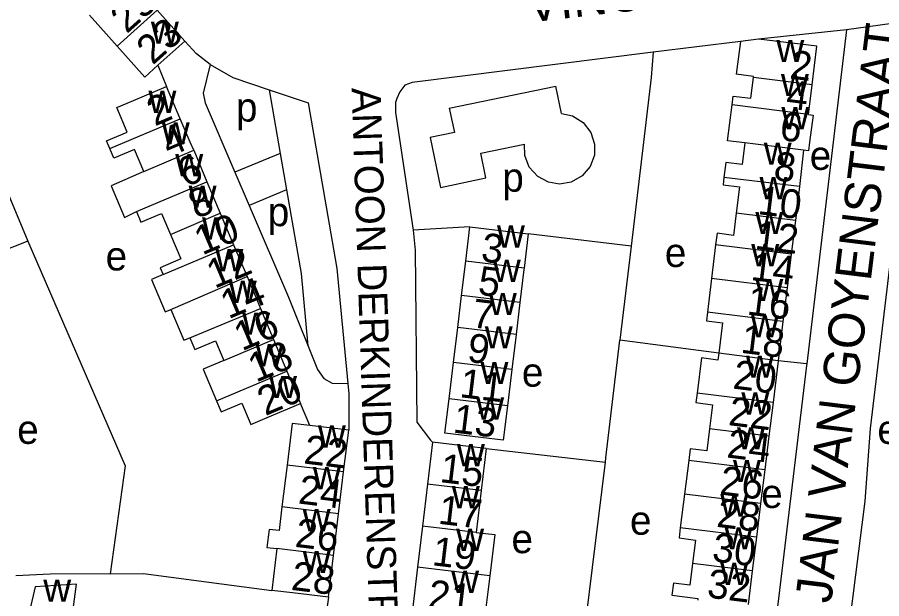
# Model space of a CAD drawing. Extents: x 161775 to 163181, y 382878 to 383925.
# Drawn here: x 162735.4 to 162855, y 383186.8 to 383267.3 of the extents above; entities that cross this region are included whole.
import ezdxf

# ---------------------------------------------------------------- set-up
doc = ezdxf.new("R2010")
doc.units = 0
for name, color, linetype in [('BLT_Basislijn', 7, 'Continuous'), ('BLT_Bebouwing', 7, 'Continuous'), ('BLT_Centroide', 7, 'Continuous'), ('BLT_Huisnummer', 7, 'Continuous'), ('BLT_Huisnummer_ tussenligend', 7, 'Continuous'), ('BLT_Onderverdeling_panden', 7, 'Continuous'), ('BLT_Straatnaam', 7, 'Continuous'), ('BLT_Vlakafsluiter', 7, 'Continuous')]:
    doc.layers.add(name, color=color, linetype=linetype)

msp = doc.modelspace()

# ---------------------------------------------------------------- linework, layer by layer
at = {"layer": 'BLT_Basislijn'}
for p, q in [((162850.08, 383265.57), (162837.91, 383264.26)), ((162835.43, 383263.94), (162823.34, 383262.45)), ((162754.83, 383260.65), (162756.03, 383257.73)), ((162795.14, 383254.7), (162809.86, 383257.75)), ((162810.65, 383253.97), (162809.86, 383257.75)), ((162795.14, 383254.7), (162795.84, 383251.34)), ((162795.84, 383251.34), (162792.48, 383250.64)), ((162792.48, 383250.64), (162793.91, 383243.74)), ((162799.49, 383248.49), (162805.55, 383249.74)), ((162771.75, 383248.43), (162765.48, 383245.83)), ((162771.75, 383248.43), (162772.63, 383243.38)), ((162800.21, 383245.04), (162799.49, 383248.49)), ((162765.48, 383245.83), (162767.45, 383241.23)), ((162793.91, 383243.74), (162800.21, 383245.04)), ((162772.63, 383243.38), (162767.45, 383241.23)), ((162797.99, 383238.29), (162790.12, 383237.8)), ((162820.29, 383235.6), (162806.06, 383237.31)), ((162736.81, 383236.3), (162732.43, 383234.55)), ((162820.29, 383235.6), (162818.74, 383222.6)), ((162832.43, 383220.77), (162818.74, 383222.6)), ((162844.59, 383219.29), (162840.64, 383219.75)), ((162775.84, 383210.77), (162774.56, 383213.82)), ((162800.24, 383207.59), (162816.74, 383205.68)), ((162813.91, 383182.7), (162816.74, 383205.68)), ((162778.41, 383186.99), (162778.14, 383185.09))]:
    msp.add_line(p, q, dxfattribs=at)
for points in [[(162850.08, 383265.57), (162844.59, 383219.29)], [(162762.03, 383260.74), (162760.17, 383262.24), (162758.54, 383263.98)], [(162823.34, 383262.45), (162789.99, 383258.28), (162789, 383257.91), (162788.28, 383256.97), (162787.9, 383256.06), (162787.71, 383255.49), (162787.71, 383254.12), (162790.12, 383237.8)], [(162823.34, 383262.45), (162823.08, 383258.97), (162820.29, 383235.6)], [(162762.03, 383260.74), (162761.1, 383256.8), (162761.38, 383255.43), (162765.48, 383245.83)], [(162762.03, 383260.74), (162765.2, 383258.95), (162770.21, 383257.25)], [(162724.18, 383256.84), (162732, 383247.83), (162736.81, 383236.3)], [(162770.21, 383257.25), (162775.6, 383255.43), (162779.6, 383232.5), (162781.09, 383216.58)], [(162770.21, 383257.25), (162771.75, 383248.43)], [(162810.65, 383253.97), (162812.2, 383253.63), (162813.66, 383252.73), (162814.74, 383251.35), (162815.25, 383249.74), (162815.21, 383248.19), (162814.65, 383246.65), (162813.52, 383245.32), (162812.01, 383244.46), (162810.39, 383244.19), (162808.86, 383244.44), (162807.38, 383245.24), (162806.21, 383246.55), (162805.6, 383248.16), (162805.55, 383249.74)], [(162857.59, 383245.49), (162853.35, 383210.37), (162852.65, 383200.3), (162849.19, 383172.97), (162849.18, 383172.77)], [(162772.63, 383243.38), (162774.64, 383231.83), (162775.57, 383221.82)], [(162767.45, 383241.23), (162772.87, 383228.55), (162776.89, 383218.54), (162777.8, 383217.28), (162778.95, 383216.64), (162781.09, 383216.58)], [(162790.12, 383237.8), (162790.42, 383235.04), (162790.63, 383211.25), (162792.55, 383208.75), (162792.83, 383208.48)], [(162736.81, 383236.3), (162750.28, 383205.17), (162748.23, 383190.26)], [(162816.74, 383205.68), (162816.81, 383206.28), (162818.74, 383222.6)], [(162844.59, 383219.29), (162844.56, 383219.06), (162840.12, 383182.2), (162838.49, 383174.01)], [(162781.09, 383216.58), (162781.24, 383215.18), (162781.23, 383210.12)], [(162748.23, 383190.26), (162739.9, 383190.21), (162735.14, 383189.96)], [(162748.23, 383190.26), (162752.83, 383190.3), (162770.58, 383187.95)]]:
    msp.add_lwpolyline(points, dxfattribs=at)
at = {"layer": 'BLT_Bebouwing'}
for p, q in [((162749.17, 383263.3), (162745.34, 383267.58)), ((162754.71, 383268.26), (162758.54, 383263.98)), ((162758.54, 383263.98), (162754.83, 383260.65)), ((162845.34, 383257.94), (162845.99, 383263.27)), ((162757.92, 383253.24), (162756.03, 383257.73)), ((162844.83, 383253.83), (162845.34, 383257.94)), ((162759.77, 383248.87), (162761.61, 383244.51)), ((162844.16, 383248.89), (162843.6, 383243.87)), ((162761.61, 383244.51), (162763.44, 383240.16)), ((162843.6, 383243.87), (162843.02, 383239.17)), ((162763.44, 383240.16), (162765.3, 383235.77)), ((162843.02, 383239.17), (162842.45, 383234.5)), ((162797.41, 383233.52), (162797.99, 383238.29)), ((162797.99, 383238.29), (162806.06, 383237.31)), ((162806.06, 383237.31), (162805.48, 383232.55)), ((162765.3, 383235.77), (162767.15, 383231.38)), ((162831.98, 383235.8), (162831.4, 383231.13)), ((162842.45, 383234.5), (162841.87, 383229.84)), ((162796.84, 383228.76), (162797.41, 383233.52)), ((162767.15, 383231.38), (162769, 383226.99)), ((162831.4, 383231.13), (162830.88, 383226.46)), ((162841.87, 383229.84), (162841.3, 383225.18)), ((162796.31, 383224.36), (162796.84, 383228.76)), ((162804.9, 383227.79), (162804.37, 383223.39)), ((162769, 383226.99), (162770.82, 383222.67)), ((162795.72, 383219.49), (162796.31, 383224.36)), ((162841.3, 383225.18), (162840.64, 383219.75)), ((162804.37, 383223.39), (162803.78, 383218.52)), ((162770.82, 383222.67), (162772.67, 383218.3)), ((162795.11, 383214.47), (162795.72, 383219.49)), ((162840.64, 383219.75), (162839.93, 383213.97)), ((162772.67, 383218.3), (162774.56, 383213.82)), ((162803.78, 383218.52), (162803.18, 383213.5)), ((162839.93, 383213.97), (162839.35, 383209.3)), ((162781.23, 383210.12), (162775.84, 383210.77)), ((162780.52, 383204.34), (162781.23, 383210.12)), ((162839.35, 383209.3), (162838.78, 383204.64)), ((162792.83, 383208.48), (162792.13, 383202.67)), ((162800.24, 383207.59), (162799.55, 383201.78)), ((162772.69, 383205.29), (162771.99, 383199.51)), ((162828.26, 383205.93), (162827.68, 383201.27)), ((162779.82, 383198.55), (162780.52, 383204.34)), ((162838.78, 383204.64), (162838.21, 383199.97)), ((162792.13, 383202.67), (162791.43, 383196.86)), ((162799.55, 383201.78), (162798.85, 383195.97)), ((162827.68, 383201.27), (162827.1, 383196.6)), ((162838.21, 383199.97), (162837.64, 383195.31)), ((162779.12, 383192.77), (162779.82, 383198.55)), ((162791.43, 383196.86), (162790.75, 383191.15)), ((162837.64, 383195.31), (162837.06, 383190.64)), ((162771.28, 383193.73), (162770.58, 383187.95)), ((162778.41, 383186.99), (162779.12, 383192.77)), ((162790.75, 383191.15), (162790.04, 383185.25)), ((162837.06, 383190.64), (162836.49, 383185.98)), ((162800.74, 383189.96), (162800.03, 383184.05))]:
    msp.add_line(p, q, dxfattribs=at)
for points in [[(162835.43, 383263.94), (162834.84, 383259.4)], [(162837.91, 383264.26), (162835.43, 383263.94)], [(162845.99, 383263.27), (162837.91, 383264.26)], [(162754.83, 383260.65), (162753, 383259.02), (162749.17, 383263.3)], [(162834.27, 383255.15), (162834.42, 383256.38), (162836.86, 383256.07), (162837.25, 383258.95)], [(162837.25, 383258.95), (162837.24, 383259.1), (162834.84, 383259.4)], [(162748.17, 383249.12), (162747.72, 383250.17), (162750.58, 383251.38), (162749.13, 383254.8), (162751.43, 383255.78), (162756.03, 383257.73)], [(162836.05, 383249.9), (162833.65, 383250.2), (162834.27, 383255.15)], [(162759.77, 383248.87), (162759.29, 383250), (162757.92, 383253.24)], [(162844.83, 383253.83), (162845.47, 383253.74), (162845, 383250), (162844.85, 383248.8), (162844.16, 383248.89)], [(162836.05, 383249.9), (162835.68, 383246.92), (162833.4, 383247.2), (162833.14, 383245.12)], [(162752.87, 383245.96), (162751.59, 383249), (162748.73, 383247.79), (162748.17, 383249.12)], [(162752.87, 383245.96), (162748.37, 383243.94), (162750.21, 383239.58), (162751.86, 383240.39)], [(162833.14, 383245.12), (162833.01, 383244.08), (162835.29, 383243.8), (162834.84, 383240.18)], [(162751.86, 383240.39), (162752.48, 383238.92), (162755.34, 383240.13), (162756.56, 383237.23)], [(162834.84, 383240.18), (162834.45, 383237.09), (162832.18, 383237.38), (162831.98, 383235.8)], [(162756.56, 383237.23), (162758, 383233.83), (162755.14, 383232.62), (162755.55, 383231.66)], [(162805.48, 383232.55), (162805.46, 383232.35), (162804.9, 383227.79)], [(162755.55, 383231.66), (162753.94, 383230.98), (162755.83, 383226.5), (162756.62, 383226.83)], [(162756.62, 383226.83), (162758.42, 383222.58), (162759.24, 383222.93)], [(162830.88, 383226.46), (162830.73, 383225.27), (162832.95, 383225), (162832.43, 383220.77)], [(162759.24, 383222.93), (162759.93, 383221.28), (162762.8, 383222.49), (162763.95, 383219.77)], [(162832.43, 383220.77), (162832.31, 383219.83), (162830.03, 383220.12), (162829.42, 383215.26)], [(162763.95, 383219.77), (162761.09, 383218.56), (162762.93, 383214.2)], [(162829.42, 383215.26), (162829.26, 383213.94), (162831.54, 383213.65), (162831.12, 383210.32)], [(162762.93, 383214.2), (162763.59, 383212.65), (162766.45, 383213.86), (162767.69, 383210.92), (162769.95, 383211.87), (162774.56, 383213.82)], [(162803.18, 383213.5), (162802.6, 383208.73), (162799.5, 383209.11), (162794.53, 383209.71), (162795.11, 383214.47)], [(162775.84, 383210.77), (162773.4, 383211.07), (162772.69, 383205.29)], [(162831.12, 383210.32), (162830.75, 383207.27), (162828.46, 383207.56), (162828.26, 383205.93)], [(162800.24, 383207.59), (162797.8, 383207.88), (162792.83, 383208.48)], [(162771.99, 383199.51), (162771.59, 383196.22), (162770.2, 383196.39), (162769.89, 383193.9), (162771.28, 383193.73)], [(162827.1, 383196.6), (162826.93, 383195.2), (162829.21, 383194.91), (162828.81, 383191.66)], [(162798.85, 383195.97), (162801.43, 383195.7), (162800.74, 383189.96)], [(162828.81, 383191.66), (162828.43, 383188.67), (162826.15, 383188.95), (162825.94, 383187.28), (162829.55, 383186.83), (162829.52, 383186.6)], [(162737.82, 383188.43), (162737.11, 383185.26), (162742.91, 383183.96), (162743.56, 383188.81), (162737.82, 383188.43)], [(162778.41, 383186.99), (162773.45, 383187.6), (162770.58, 383187.95)]]:
    msp.add_lwpolyline(points, dxfattribs=at)
at = {"layer": 'BLT_Onderverdeling_panden'}
for p, q in [((162749.17, 383263.3), (162754.71, 383268.26)), ((162845.34, 383257.94), (162837.25, 383258.95)), ((162844.83, 383253.83), (162834.27, 383255.15)), ((162748.17, 383249.12), (162757.92, 383253.24)), ((162752.87, 383245.96), (162759.77, 383248.87)), ((162751.86, 383240.39), (162761.61, 383244.51)), ((162843.6, 383243.87), (162833.14, 383245.12)), ((162756.56, 383237.23), (162763.44, 383240.16)), ((162843.02, 383239.17), (162834.84, 383240.18)), ((162755.55, 383231.66), (162765.3, 383235.77)), ((162842.45, 383234.5), (162831.98, 383235.8)), ((162805.48, 383232.55), (162797.41, 383233.52)), ((162756.62, 383226.83), (162767.15, 383231.38)), ((162841.87, 383229.84), (162831.4, 383231.13)), ((162804.9, 383227.79), (162796.84, 383228.76)), ((162759.24, 383222.93), (162769, 383226.99)), ((162841.3, 383225.18), (162830.88, 383226.46)), ((162804.37, 383223.39), (162796.31, 383224.36)), ((162763.95, 383219.77), (162770.82, 383222.67)), ((162840.64, 383219.75), (162832.43, 383220.77)), ((162803.78, 383218.52), (162795.72, 383219.49)), ((162762.93, 383214.2), (162772.67, 383218.3)), ((162839.93, 383213.97), (162829.42, 383215.26)), ((162803.18, 383213.5), (162795.11, 383214.47)), ((162839.35, 383209.3), (162831.12, 383210.32)), ((162780.52, 383204.34), (162772.69, 383205.29)), ((162838.78, 383204.64), (162828.26, 383205.93)), ((162799.55, 383201.78), (162792.13, 383202.67)), ((162838.21, 383199.97), (162827.68, 383201.27)), ((162779.82, 383198.55), (162771.99, 383199.51)), ((162798.85, 383195.97), (162791.43, 383196.86)), ((162837.64, 383195.31), (162827.1, 383196.6)), ((162779.12, 383192.77), (162771.28, 383193.73)), ((162800.74, 383189.96), (162790.75, 383191.15)), ((162837.06, 383190.64), (162828.81, 383191.66))]:
    msp.add_line(p, q, dxfattribs=at)
msp.add_lwpolyline([(162844.16, 383248.89), (162836.05, 383249.9)], dxfattribs=at)
at = {"layer": 'BLT_Vlakafsluiter'}
msp.add_line((162860.47, 383267), (162850.08, 383265.57), dxfattribs=at)

# ---------------------------------------------------------------- texts
at = {"layer": 'BLT_Centroide'}
for s, p in [('w', (162753.85, 383263.62)), ('w', (162840.39, 383261.09)), ('w', (162841.02, 383256.38)), ('w', (162753.51, 383254.06)), ('p', (162765.62, 383252.85)), ('w', (162841.09, 383251.78)), ('w', (162755.36, 383249.69)), ('w', (162838.65, 383246.88)), ('e', (162845.01, 383246.16)), ('w', (162757.22, 383245.28)), ('p', (162802.47, 383243.14)), ('w', (162838.07, 383242.09)), ('w', (162759.07, 383240.91)), ('p', (162770.02, 383238.37)), ('w', (162837.48, 383237.28)), ('w', (162760.93, 383236.5)), ('w', (162801.73, 383235.41)), ('e', (162747.59, 383232.24)), ('w', (162762.77, 383232.12)), ('e', (162824.96, 383232.72)), ('w', (162836.92, 383232.81)), ('w', (162801.16, 383230.66)), ('w', (162764.63, 383227.75)), ('w', (162837.49, 383228)), ('w', (162800.61, 383226.06)), ('w', (162766.48, 383223.34)), ('w', (162836.87, 383222.97)), ('w', (162800.05, 383221.44)), ('w', (162768.34, 383218.97)), ('w', (162799.45, 383216.5)), ('w', (162836.17, 383217.38)), ('e', (162805.18, 383216.15)), ('w', (162770.2, 383214.56)), ('w', (162798.86, 383211.59)), ('w', (162835.55, 383212.28)), ('e', (162735.35, 383208.23)), ('e', (162854.37, 383208.23)), ('w', (162776.96, 383207.72)), ('w', (162834.95, 383207.47)), ('w', (162796.19, 383205.12)), ('w', (162776.26, 383201.94)), ('w', (162834.39, 383202.94)), ('w', (162795.49, 383199.31)), ('e', (162838.29, 383199.35)), ('w', (162832.64, 383198.16)), ('w', (162774.85, 383196.12)), ('e', (162820.14, 383195.65)), ('w', (162833.23, 383193.62)), ('w', (162796.09, 383193.41)), ('e', (162803.74, 383193.1)), ('w', (162774.85, 383190.34)), ('w', (162795.39, 383187.59)), ('w', (162832.63, 383188.69)), ('w', (162738.96, 383186.38))]:
    msp.add_text(s, height=4, dxfattribs=at).set_placement(p)
at = {"layer": 'BLT_Huisnummer'}
for s, rotation, p in [('25', 41.8332, (162750.5, 383264.93)), ('23', 41.8332, (162754.1, 383260.59)), ('2', 352.8824, (162842.12, 383258.82)), ('2', 22.9213, (162754.38, 383252.16)), ('6', 352.8793, (162840.73, 383250.31)), ('6', 22.9169, (162758.64, 383243.71)), ('10', 352.8837, (162837.71, 383240.05)), ('10', 22.9166, (162760.95, 383234.3)), ('3', 353.1085, (162799.42, 383233.51)), ('14', 352.8811, (162836.74, 383230.93)), ('14', 22.9242, (162764.58, 383225.46)), ('7', 353.1085, (162798.14, 383224.39)), ('18', 352.8828, (162835.35, 383220.86)), ('18', 22.9242, (162768.39, 383216.68)), ('20', 352.8828, (162834.26, 383215.9)), ('20', 22.9015, (162769.67, 383212.06)), ('13', 353.1081, (162795.54, 383209.81)), ('24', 352.8811, (162833.42, 383206.36)), ('22', 353.0597, (162774.89, 383205.53)), ('15', 353.1651, (162793.72, 383202.95)), ('28', 352.8828, (162832.01, 383196.76)), ('26', 353.0597, (162773.68, 383193.99)), ('19', 353.1651, (162792.65, 383191.44)), ('28', 353.0612, (162773.14, 383188.03)), ('32', 352.8776, (162830.68, 383186.98)), ('21', 353.1663, (162792.06, 383185.49))]:
    msp.add_text(s, height=4, rotation=rotation, dxfattribs=at).set_placement(p)
at = {"layer": 'BLT_Huisnummer_ tussenligend'}
for s, rotation, p in [('4', 352.8824, (162841.62, 383254.71)), ('4', 22.9213, (162756.36, 383247.92)), ('8', 352.8793, (162839.89, 383244.78)), ('8', 22.9169, (162760.14, 383239.33)), ('12', 352.8837, (162837.3, 383235.25)), ('12', 22.9166, (162762.66, 383229.67)), ('5', 353.1085, (162798.99, 383228.91)), ('16', 352.8811, (162836.22, 383226.15)), ('16', 22.9242, (162766.44, 383221.03)), ('9', 353.1085, (162797.51, 383219.61)), ('11', 353.1081, (162796.46, 383214.71)), ('22', 352.8811, (162833.65, 383210.84)), ('26', 352.8828, (162832.43, 383201.24)), ('24', 353.0597, (162774.13, 383199.99)), ('17', 353.1651, (162793.49, 383197.19)), ('30', 352.8776, (162831.39, 383191.99))]:
    msp.add_text(s, height=4, rotation=rotation, dxfattribs=at).set_placement(p)
at = {"layer": 'BLT_Straatnaam'}
for s, height, rotation, p in [('VINCENT VAN GOGHSTRAAT', 5, 6.5128, (162806.13, 383266.55)), ('JAN VAN GOYENSTRAAT', 5, 82.9955, (162847.96, 383186.04)), ('ANTOON DERKINDERENSTRAAT', 4, 271.8942, (162781.62, 383257.51))]:
    msp.add_text(s, height=height, rotation=rotation, dxfattribs=at).set_placement(p)

doc.saveas('drawing.dxf')
